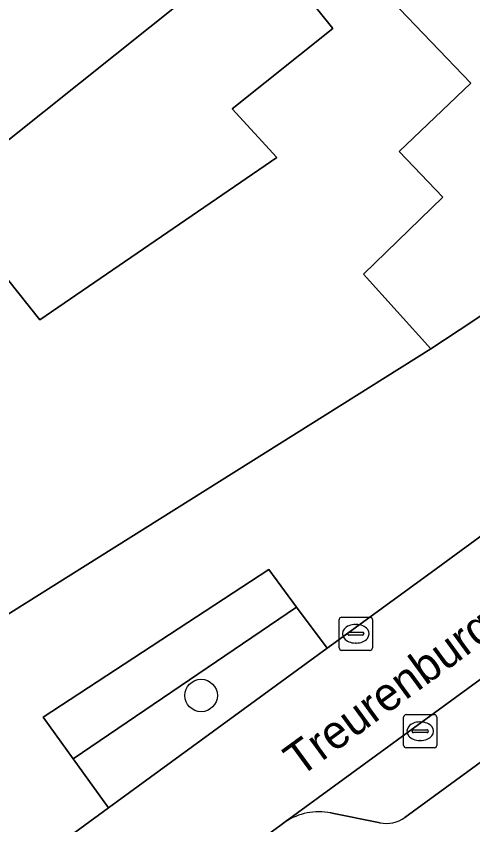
# Model space of a CAD drawing. Extents: x 161772 to 163126, y 383092 to 383917.
# Drawn here: x 162207.36 to 162221.11, y 383316.84 to 383341.19 of the extents above; entities that cross this region are included whole.
import ezdxf

# ---------------------------------------------------------------- set-up
doc = ezdxf.new("R2010")
doc.units = 0
for name, color, linetype in [('IMGEO_Boom', 7, 'Continuous'), ('IMGEO_Erf', 7, 'Continuous'), ('IMGEO_Groenvoorziening', 7, 'Continuous'), ('IMGEO_Kolk', 7, 'Continuous'), ('IMGEO_Openbare_ruimte_label', 7, 'Continuous'), ('IMGEO_Pand', 7, 'Continuous'), ('IMGEO_Parkeervlak_open', 7, 'Continuous'), ('IMGEO_Rijbaan_lokaal_open', 7, 'Continuous'), ('IMGEO_Voetpad_open', 7, 'Continuous')]:
    doc.layers.add(name, color=color, linetype=linetype)

msp = doc.modelspace()

# ---------------------------------------------------------------- linework, layer by layer
at = {"layer": 'IMGEO_Boom'}
msp.add_circle((162212.931, 383320.732), 0.489, dxfattribs=at)
at = {"layer": 'IMGEO_Erf'}
msp.add_lwpolyline([(162210.75, 383350.151), (162212.893, 383352.202), (162216.505, 383355.659), (162222.018, 383349.899), (162218.406, 383346.442), (162216.263, 383344.391), (162214.839, 383343.394), (162216.893, 383340.821), (162213.867, 383338.405), (162215.216, 383336.937), (162208.071, 383332.045), (162205.057, 383335.822), (162212.428, 383341.705), (162212.775, 383341.948), (162209.166, 383345.61), (162211.986, 383348.86)], close=True, dxfattribs=at)
msp.add_lwpolyline([(162206.249, 383322.642), (162219.852, 383331.173), (162217.82, 383333.426), (162220.215, 383335.738), (162218.896, 383337.116), (162221.05, 383339.177), (162217.472, 383342.916)], dxfattribs=at)
at = {"layer": 'IMGEO_Groenvoorziening'}
for points in [[(162215.808, 383323.394), (162214.966, 383324.53), (162208.173, 383320.08), (162209.075, 383318.827)], [(162216.726, 383322.155), (162215.808, 383323.394), (162209.075, 383318.827), (162210.137, 383317.35)]]:
    msp.add_lwpolyline(points, close=True, dxfattribs=at)
at = {"layer": 'IMGEO_Kolk'}
for p, q in [((162217.088, 383322.166), (162217.088, 383323.018)), ((162217.163, 383323.092), (162218.015, 383323.092)), ((162217.576, 383322.872), (162217.601, 383322.872)), ((162218.089, 383323.018), (162218.089, 383322.166)), ((162217.39, 383322.635), (162217.788, 383322.635)), ((162217.347, 383322.586), (162217.347, 383322.598)), ((162217.785, 383322.549), (162217.387, 383322.549)), ((162217.831, 383322.598), (162217.831, 383322.586)), ((162217.599, 383322.312), (162217.574, 383322.312)), ((162218.015, 383322.092), (162217.163, 383322.092)), ((162219.029, 383319.23), (162219.029, 383320.082)), ((162219.104, 383320.156), (162219.956, 383320.156)), ((162220.03, 383320.082), (162220.03, 383319.23)), ((162219.331, 383319.699), (162219.729, 383319.699)), ((162219.517, 383319.936), (162219.542, 383319.936)), ((162219.288, 383319.65), (162219.288, 383319.662)), ((162219.726, 383319.613), (162219.328, 383319.613)), ((162219.772, 383319.662), (162219.772, 383319.65)), ((162219.54, 383319.376), (162219.515, 383319.376)), ((162219.956, 383319.156), (162219.104, 383319.156))]:
    msp.add_line(p, q, dxfattribs=at)
for points in [[(162217.088, 383322.166), (162217.088, 383323.018)], [(162217.163, 383323.092), (162218.015, 383323.092)], [(162218.089, 383323.018), (162218.089, 383322.166)], [(162218.015, 383322.092), (162217.163, 383322.092)], [(162219.029, 383319.23), (162219.029, 383320.082)], [(162219.104, 383320.156), (162219.956, 383320.156)], [(162220.03, 383320.082), (162220.03, 383319.23)], [(162219.956, 383319.156), (162219.104, 383319.156)]]:
    msp.add_lwpolyline(points, dxfattribs=at)
for centre, radius, start, end in [((162217.165, 383323.016), 0.0765, 91.552, 178.448), ((162217.165, 383323.016), 0.0765, 91.552, 178.448), ((162218.013, 383323.016), 0.0765, 1.552, 88.448), ((162218.013, 383323.016), 0.0765, 1.552, 88.448), ((162217.387, 383322.595), 0.0403, 85.8775, 175.7526), ((162217.792, 383322.597), 0.0386, 1.7309, 96.639), ((162217.384, 383322.585), 0.0366, 178.938, 274.7102), ((162217.788, 383322.592), 0.043, 264.8664, 352.4533), ((162217.165, 383322.168), 0.0765, 181.552, 268.448), ((162217.165, 383322.168), 0.0765, 181.552, 268.448), ((162218.013, 383322.168), 0.0765, 271.552, 358.448), ((162218.013, 383322.168), 0.0765, 271.552, 358.448), ((162219.106, 383320.08), 0.0765, 91.552, 178.448), ((162219.106, 383320.08), 0.0765, 91.552, 178.448), ((162219.954, 383320.08), 0.0765, 1.552, 88.448), ((162219.954, 383320.08), 0.0765, 1.552, 88.448), ((162219.328, 383319.659), 0.0403, 85.8775, 175.7526), ((162219.733, 383319.661), 0.0386, 1.7309, 96.639), ((162219.325, 383319.649), 0.0366, 178.938, 274.7102), ((162219.729, 383319.656), 0.043, 264.8664, 352.4533), ((162219.106, 383319.232), 0.0765, 181.552, 268.448), ((162219.106, 383319.232), 0.0765, 181.552, 268.448), ((162219.954, 383319.232), 0.0765, 271.552, 358.448), ((162219.954, 383319.232), 0.0765, 271.552, 358.448)]:
    msp.add_arc(centre, radius, start, end, dxfattribs=at)
for centre, major_axis, ratio, start_param, end_param in [((162217.575, 383322.592), (-0.387, 0.002), 0.722429, 4.712389, 7.853982), ((162217.6, 383322.592), (-0.39, 0.002), 0.717154, 1.570796, 4.712389), ((162219.516, 383319.656), (-0.387, 0.002), 0.722429, 4.712389, 7.853982), ((162219.541, 383319.656), (-0.39, 0.002), 0.717154, 1.570796, 4.712389)]:
    msp.add_ellipse(centre, major_axis=major_axis, ratio=ratio, start_param=start_param, end_param=end_param, dxfattribs=at)
at = {"layer": 'IMGEO_Pand'}
for points in [[(162229.421, 383342.648), (162223.574, 383348.756), (162219.962, 383345.299), (162217.472, 383342.916), (162221.05, 383339.177), (162218.896, 383337.116), (162220.215, 383335.738), (162217.82, 383333.426), (162219.852, 383331.173), (162220.701, 383331.735), (162225.23, 383334.734), (162223.28, 383336.772)], [(162213.867, 383338.405), (162216.893, 383340.821), (162214.839, 383343.394), (162212.775, 383341.948), (162212.428, 383341.705), (162205.057, 383335.822), (162208.071, 383332.045), (162215.216, 383336.937)]]:
    msp.add_lwpolyline(points, close=True, dxfattribs=at)
at = {"layer": 'IMGEO_Parkeervlak_open'}
for points in [[(162234.981, 383331.174), (162215.461, 383316.922)], [(162219.066, 383317.059), (162233.649, 383327.709)], [(162216.832, 383317.196), (162218.318, 383316.897)]]:
    msp.add_lwpolyline(points, dxfattribs=at)
for centre, radius, start, end in [((162216.476, 383315.413), 1.818, 78.6944, 123.9094), ((162218.506, 383317.835), 0.957, 258.6527, 305.7878)]:
    msp.add_arc(centre, radius, start, end, dxfattribs=at)
at = {"layer": 'IMGEO_Rijbaan_lokaal_open'}
for points in [[(162236.001, 383336.216), (162235.267, 383335.684), (162232.588, 383333.742), (162221.778, 383325.843), (162220.009, 383324.55), (162216.752, 383322.174), (162216.726, 383322.155), (162210.137, 383317.35), (162202.551, 383311.798), (162200.084, 383309.99), (162197.956, 383308.43), (162188.266, 383301.328), (162187.302, 383300.684), (162186.204, 383299.95)], [(162180.728, 383298.277), (162180.472, 383298.312), (162173.647, 383293.553), (162172.965, 383293.041), (162173.143, 383292.801), (162176.419, 383288.739), (162187.69, 383296.571), (162187.908, 383296.732), (162189.561, 383297.948), (162191.226, 383299.172), (162204.388, 383308.839), (162205.967, 383309.992), (162215.343, 383316.836), (162215.461, 383316.922), (162234.981, 383331.174)]]:
    msp.add_lwpolyline(points, dxfattribs=at)
at = {"layer": 'IMGEO_Voetpad_open'}
for points in [[(162235.652, 383344.393), (162234.551, 383340.908), (162225.23, 383334.734), (162220.701, 383331.735), (162219.852, 383331.173), (162206.249, 383322.642), (162203.496, 383320.915), (162200.785, 383319.215), (162198.292, 383317.652), (162195.048, 383315.551), (162192.644, 383313.994), (162189.851, 383312.185), (162181.014, 383306.463), (162181.367, 383306.033), (162178.959, 383304.304), (162174.427, 383302.411), (162177.4, 383299.583)], [(162233.649, 383327.709), (162219.066, 383317.059)], [(162208.173, 383320.08), (162214.966, 383324.53), (162215.808, 383323.394), (162216.726, 383322.155), (162216.752, 383322.174), (162220.009, 383324.55), (162221.778, 383325.843)], [(162186.204, 383299.95), (162187.302, 383300.684), (162186.274, 383302.232), (162189.204, 383304.422), (162189.288, 383304.297), (162194.426, 383308.059), (162192.914, 383310.136), (162197.676, 383313.27), (162199.068, 383311.373), (162200.084, 383309.99), (162202.551, 383311.798), (162210.137, 383317.35), (162209.075, 383318.827), (162208.173, 383320.08)], [(162218.318, 383316.897), (162216.832, 383317.196)], [(162215.461, 383316.922), (162215.343, 383316.836), (162205.967, 383309.992), (162207.18, 383308.262), (162203.444, 383305.484), (162203.329, 383305.651)]]:
    msp.add_lwpolyline(points, dxfattribs=at)
for centre, radius, start, end in [((162216.476, 383315.413), 1.818, 78.6944, 123.9094), ((162218.506, 383317.835), 0.957, 258.6527, 305.7878)]:
    msp.add_arc(centre, radius, start, end, dxfattribs=at)

# ---------------------------------------------------------------- texts
at = {"layer": 'IMGEO_Openbare_ruimte_label'}
msp.add_text('Treurenburgstraat', height=1, rotation=36.1368, dxfattribs=at).set_placement((162215.904, 383318.255))

doc.saveas('drawing.dxf')
